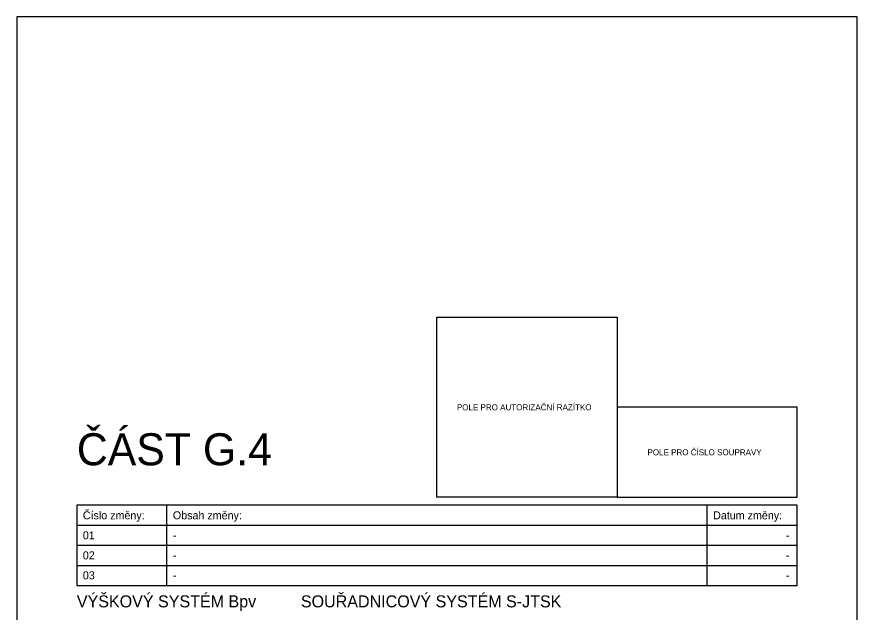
# Model space of a CAD drawing. Extents: x 2039 to 2249, y 760 to 1057.
# Drawn here: x 2038.7 to 2248.7, y 908.2 to 1056.9 of the extents above; entities that cross this region are included whole.
import ezdxf

# ---------------------------------------------------------------- set-up
doc = ezdxf.new("R2010")
doc.units = 0
for name, color, linetype in [('101_PRIKOP', 7, 'Continuous'), ('104_SVODIDLO', 7, 'Continuous'), ('104_ZPEVNENI', 7, 'Continuous'), ('106_KRAJNICE', 7, 'Continuous'), ('120_ZPEVNENI', 7, 'Continuous')]:
    doc.layers.add(name, color=color, linetype=linetype)

msp = doc.modelspace()

# ---------------------------------------------------------------- linework, layer by layer
at = {"layer": '104_SVODIDLO'}
for points in [[(2188.65, 936.87), (2143.65, 936.87), (2143.65, 981.87), (2188.65, 981.87)], [(2188.65, 936.87), (2233.65, 936.87), (2233.65, 959.37), (2188.65, 959.37)]]:
    msp.add_lwpolyline(points, close=True, dxfattribs=at)
at = {"layer": '106_KRAJNICE'}
for p, q in [((2076.15, 914.87), (2076.15, 934.87)), ((2211.15, 914.87), (2211.15, 934.87)), ((2053.65, 929.87), (2233.65, 929.87)), ((2053.65, 924.87), (2233.65, 924.87)), ((2053.65, 919.87), (2233.65, 919.87))]:
    msp.add_line(p, q, dxfattribs=at)
msp.add_lwpolyline([(2053.65, 914.87), (2233.65, 914.87), (2233.65, 934.87), (2053.65, 934.87)], close=True, dxfattribs=at)
at = {"layer": '120_ZPEVNENI'}
msp.add_lwpolyline([(2038.65, 759.93), (2248.65, 759.93), (2248.65, 1056.93), (2038.65, 1056.93)], close=True, dxfattribs=at)

# ---------------------------------------------------------------- texts
at = {"layer": '101_PRIKOP'}
for s, p in [('01', (2055.15, 926.37)), ('-', (2077.65, 926.37)), ('-', (2230.81, 926.37)), ('02', (2055.15, 921.37)), ('-', (2077.65, 921.37)), ('-', (2230.81, 921.37)), ('03', (2055.15, 916.37)), ('-', (2077.65, 916.37)), ('-', (2230.81, 916.37))]:
    msp.add_text(s, height=2, rotation=360, dxfattribs=at).set_placement(p)
at = {"layer": '104_SVODIDLO'}
for s, p in [('POLE PRO AUTORIZAČNÍ RAZÍTKO', (2148.61, 958.62)), ('POLE PRO ČÍSLO SOUPRAVY', (2196.25, 947.37))]:
    msp.add_text(s, height=1.5, rotation=360, dxfattribs=at).set_placement(p)
at = {"layer": '104_ZPEVNENI'}
for s, p in [('Číslo změny:', (2055.15, 931.37)), ('Obsah změny:', (2077.65, 931.37)), ('Datum změny:', (2212.65, 931.37))]:
    msp.add_text(s, height=2, rotation=360, dxfattribs=at).set_placement(p)
at = {"layer": '120_ZPEVNENI'}
for s, height, p in [('ČÁST G.4', 8, (2053.65, 944.87)), ('VÝŠKOVÝ SYSTÉM Bpv', 3, (2053.65, 909.37)), ('SOUŘADNICOVÝ SYSTÉM S-JTSK', 3, (2109.64, 909.37))]:
    msp.add_text(s, height=height, dxfattribs=at).set_placement(p)

doc.saveas('drawing.dxf')
